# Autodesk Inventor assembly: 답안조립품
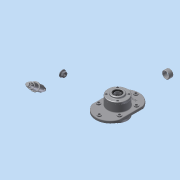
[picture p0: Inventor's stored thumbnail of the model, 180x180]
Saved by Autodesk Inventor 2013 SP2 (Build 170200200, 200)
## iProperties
Created: 2015-02
Part Number: 답안조립품
Document SubType Name: Assembly
Designer: dgall
Author: dgall
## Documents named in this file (9)
- C:\Documents and Settings\dgall\바탕 화면\450207V1029\답안조립품.iam
- C:\Documents and Settings\dgall\바탕 화면\450207V1029\1-본체.ipt
- C:\Documents and Settings\dgall\바탕 화면\450207V1029\2-커버.ipt
- C:\Documents and Settings\dgall\바탕 화면\450207V1029\8-오일실 30x42.ipt
- C:\Documents and Settings\dgall\바탕 화면\450207V1029\6-베어링 6206.ipt
- C:\Documents and Settings\dgall\바탕 화면\450207V1029\7-부시.ipt
- C:\Documents and Settings\dgall\바탕 화면\450207V1029\11-키 6x6.ipt
- C:\Documents and Settings\dgall\바탕 화면\450207V1029\9-M16-너트.ipt
- C:\Documents and Settings\dgall\바탕 화면\450207V1029\3-축.ipt
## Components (11 placed, 8 different names)
1. 1-본체:1
2. 2-커버:1
3. 2-커버:2
4. 8-8-오일실 30x42:1
5. 6-베어링 6206:1
6. 7-부시:1
7. 6-베어링 6206:2
8. 8-8-오일실 30x42:2
9. 11-키 6x6:1
10. 9-M16 너트:1
11. 3-축:1
